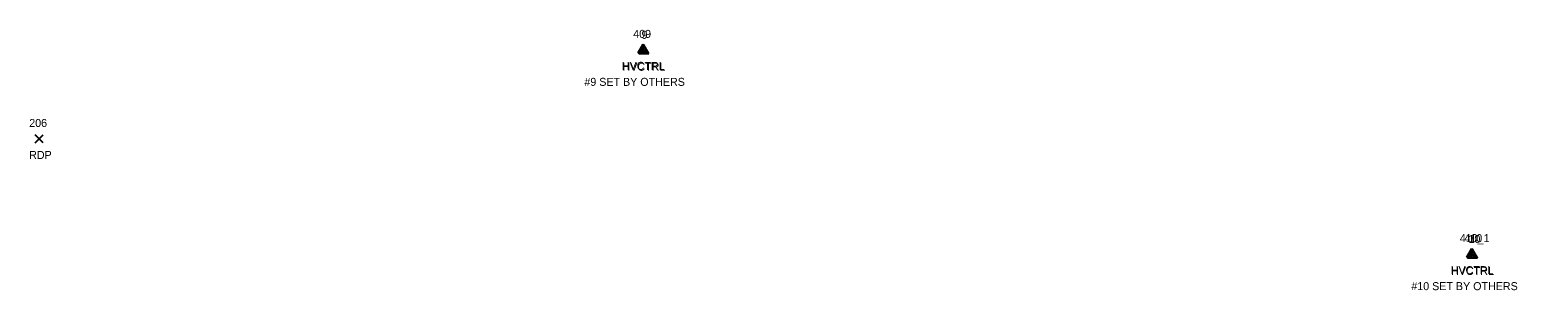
# Model space of a CAD drawing. Extents: x 1600395 to 1603269, y 874955 to 877143.
# Drawn here: x 1602436.6 to 1602808.4, y 875220.6 to 875285.7 of the extents above; entities that cross this region are included whole.
import ezdxf

# ---------------------------------------------------------------- set-up
doc = ezdxf.new("R2010")
doc.units = 0
for name, color, linetype in [('C_A', 7, 'Continuous'), ('C_C', 7, 'Continuous'), ('C_I', 7, 'Continuous'), ('CPSM', 7, 'Continuous'), ('P_A', 7, 'Continuous'), ('P_I', 7, 'Continuous'), ('P_TIC', 7, 'Continuous')]:
    doc.layers.add(name, color=color, linetype=linetype)

msp = doc.modelspace()

# ---------------------------------------------------------------- linework, layer by layer
at = {"layer": 'CPSM'}
for p, q in [((1602588.66, 875280), (1602589.91, 875282.16)), ((1602588.86, 875279.77), (1602590.11, 875281.94)), ((1602591.16, 875280), (1602589.91, 875282.16)), ((1602589.91, 875280.72), (1602589.91, 875282.16)), ((1602591.36, 875279.77), (1602590.11, 875281.94)), ((1602590.11, 875280.49), (1602590.11, 875281.94)), ((1602588.66, 875280), (1602589.91, 875280.72)), ((1602588.66, 875280), (1602591.16, 875280)), ((1602588.86, 875279.77), (1602590.11, 875280.49)), ((1602588.86, 875279.77), (1602591.36, 875279.77)), ((1602589.91, 875280.72), (1602589.91, 875280.72)), ((1602589.91, 875280.72), (1602591.16, 875280)), ((1602590.11, 875280.49), (1602590.11, 875280.49)), ((1602590.11, 875280.49), (1602591.36, 875279.77)), ((1602795.87, 875228.92), (1602797.12, 875231.09)), ((1602795.87, 875228.92), (1602797.12, 875231.09)), ((1602795.87, 875228.92), (1602797.12, 875229.64)), ((1602795.87, 875228.92), (1602797.12, 875229.64)), ((1602795.87, 875228.92), (1602798.37, 875228.92)), ((1602795.87, 875228.92), (1602798.37, 875228.92)), ((1602795.98, 875228.72), (1602797.23, 875230.89)), ((1602795.98, 875228.72), (1602797.23, 875229.44)), ((1602798.37, 875228.92), (1602797.12, 875231.09)), ((1602797.12, 875229.64), (1602797.12, 875231.09)), ((1602798.37, 875228.92), (1602797.12, 875231.09)), ((1602797.12, 875229.64), (1602797.12, 875231.09)), ((1602797.12, 875229.64), (1602797.12, 875229.64)), ((1602797.12, 875229.64), (1602798.37, 875228.92)), ((1602797.12, 875229.64), (1602797.12, 875229.64)), ((1602797.12, 875229.64), (1602798.37, 875228.92)), ((1602798.48, 875228.72), (1602797.23, 875230.89)), ((1602797.23, 875229.44), (1602797.23, 875230.89)), ((1602797.23, 875229.44), (1602797.23, 875229.44)), ((1602797.23, 875229.44), (1602798.48, 875228.72)), ((1602795.98, 875228.72), (1602798.48, 875228.72))]:
    msp.add_line(p, q, dxfattribs=at)
at = {"layer": 'P_TIC'}
for points in [[(1602437.96, 875257.44), (1602439.96, 875259.44)], [(1602439.96, 875257.44), (1602437.96, 875259.44)]]:
    msp.add_lwpolyline(points, dxfattribs=at)

# ---------------------------------------------------------------- texts
at = {"layer": 'C_A'}
for p in [(1602584.6, 875275.72), (1602584.8, 875275.49), (1602791.81, 875224.64), (1602791.81, 875224.64), (1602791.92, 875224.44)]:
    msp.add_text('HVCTRL', height=2, dxfattribs=at).set_placement(p)
at = {"layer": 'C_C'}
for s, p in [('#9 SET BY OTHERS', (1602575.25, 875271.72)), ('#10 SET BY OTHERS', (1602781.97, 875220.64))]:
    msp.add_text(s, height=2, dxfattribs=at).set_placement(p)
at = {"layer": 'C_I'}
for s, p in [('409', (1602587.46, 875283.72)), ('9', (1602589.53, 875283.49)), ('410_1', (1602794.09, 875232.64)), ('410', (1602795.23, 875232.64)), ('10', (1602796.25, 875232.44))]:
    msp.add_text(s, height=2, dxfattribs=at).set_placement(p)
at = {"layer": 'P_A'}
msp.add_text('RDP', height=2, dxfattribs=at).set_placement((1602436.45, 875253.44))
at = {"layer": 'P_I'}
msp.add_text('206', height=2, dxfattribs=at).set_placement((1602436.47, 875261.44))

doc.saveas('drawing.dxf')
